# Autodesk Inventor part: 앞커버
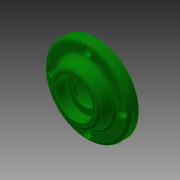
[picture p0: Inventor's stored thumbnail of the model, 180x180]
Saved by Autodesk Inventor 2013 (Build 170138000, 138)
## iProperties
Created: 2017-08
Part Number: 앞커버
Material: 알루미늄 6061
Document SubType Name: Modeling
Designer: mduedu
Density: 1 g/cm^3
Author: mduedu
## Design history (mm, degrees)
sketch "스케치1"
  geometry: C1 r 35 at (0, 0); 1 further point
  constraints: 1 centre point, 1 coincident
  dimensions: "d0" = 70 diameter of C1
extrude "돌출1" new body sketch "스케치1" distance "d1" = 8; taper "d2" = 0 deg
sketch "스케치2"
  geometry: C1 r 24 at (0, 0); 1 further point
  constraints: 1 centre point, 1 coincident
  dimensions: "d3" = 48 diameter of C1
node "작업 평면1"
sketch "스케치3"
  geometry: C1 r 20 at (0, 0); 1 further point
  constraints: 1 centre point, 1 coincident
  dimensions: "d5" = 40 diameter of C1
feature "로프트1" sketch "스케치3" dims "d6" = 0, "d7" = 90 deg, "d8" = 0, "d9" = 90 deg
sketch "스케치4"
  geometry: C1 r 24 at (0, 0) reference; 1 further point
extrude "돌출2" join sketch "스케치4" distance "d10" = 8; taper "d11" = 0 deg
hole "구멍1" diameter "d14" = 40; stored, may be unused: countersink angle "d18" = 90 deg, drill point angle "d20" = 0 deg; dims "d12" = 10, "d13" = 10, "d15" = 6, "d16" = 4, "d17" = 2, "d19" = 12
hole "구멍2" diameter "d23" = 34; stored, may be unused: countersink angle "d27" = 90 deg, drill point angle "d29" = 0 deg; dims "d21" = 10, "d22" = 10, "d24" = 6, "d25" = 4, "d26" = 2, "d28" = 3
hole "구멍3" diameter "d32" = 19; stored, may be unused: countersink angle "d36" = 90 deg, drill point angle "d38" = 0 deg; dims "d30" = 10, "d31" = 10, "d33" = 6, "d34" = 4, "d35" = 2, "d37" = 3
chamfer "모따기1" distance "d39" = 1; stored, may be unused: second distance "d40" = 2, angle "d41" = 45 deg
sketch "스케치5"
  geometry: C1 r 15 at (0, 0); 1 further point
  constraints: 1 centre point, 1 coincident
  dimensions: "d42" = 30 diameter of C1
extrude "돌출3" cut sketch "스케치5" distance "d43" = 8.3; taper "d44" = 0 deg
chamfer "모따기2" distance "d47" = 0.8; stored, may be unused: second distance "d48" = 2, angle "d49" = 30 deg
fillet "모깎기1" dims "d50" = 0.3
fillet "모깎기2" dims "d51" = 0.3
fillet "모깎기3" dims "d52" = 3
sketch "스케치6" dims "d53" = 58
  geometry: 6 further points
  constraints: 2 vertical alignment, 1 coincident, 7 other
  dimensions: "d56" = 360 deg dimension on point (0, 0) point (0, 29) (derived)
sketch "스케치9" dims "d85" = 58 (derived)
  geometry: 6 further points
  constraints: 1 coincident, 1 vertical alignment, 6 other
hole "구멍6" sketch "스케치9" at (-29, 0), (0, -29), (29, 0), (0, 29) diameter "d72" = 4.5; stored, may be unused: countersink angle "d76" = 90 deg, drill point angle "d78" = 0 deg; dims "d73" = 6, "d74" = 8, "d75" = 4.6, "d77" = 8
fillet "모깎기4" dims "d79" = 3
fillet "모깎기5" dims "d80" = 3
fillet "모깎기6" dims "d81" = 3
node "솔리드1"
